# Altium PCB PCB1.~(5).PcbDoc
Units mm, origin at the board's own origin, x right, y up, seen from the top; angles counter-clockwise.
Board outline 152.4 x 101.6 mm, 2 copper layers (Top Layer, Bottom Layer); 19 components, 17 nets, 64 pads, 0 vias.
Unrouted connection lines stored in the file: 41.
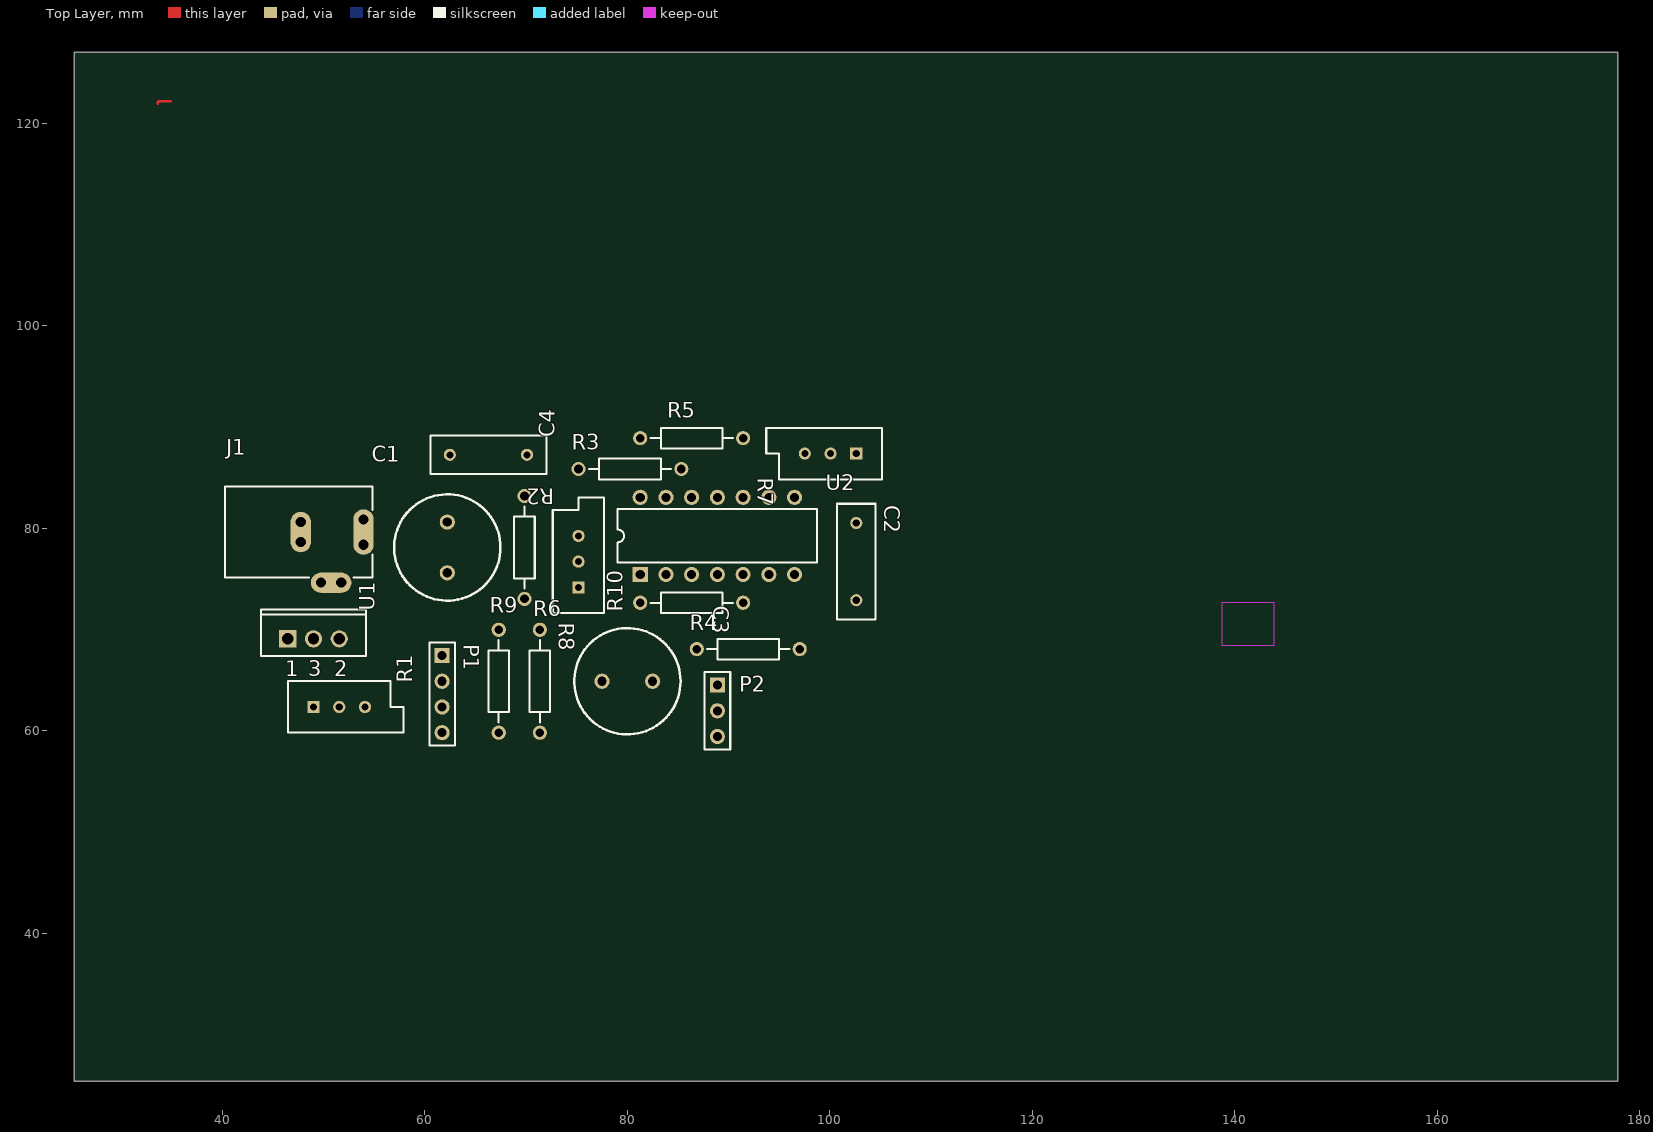
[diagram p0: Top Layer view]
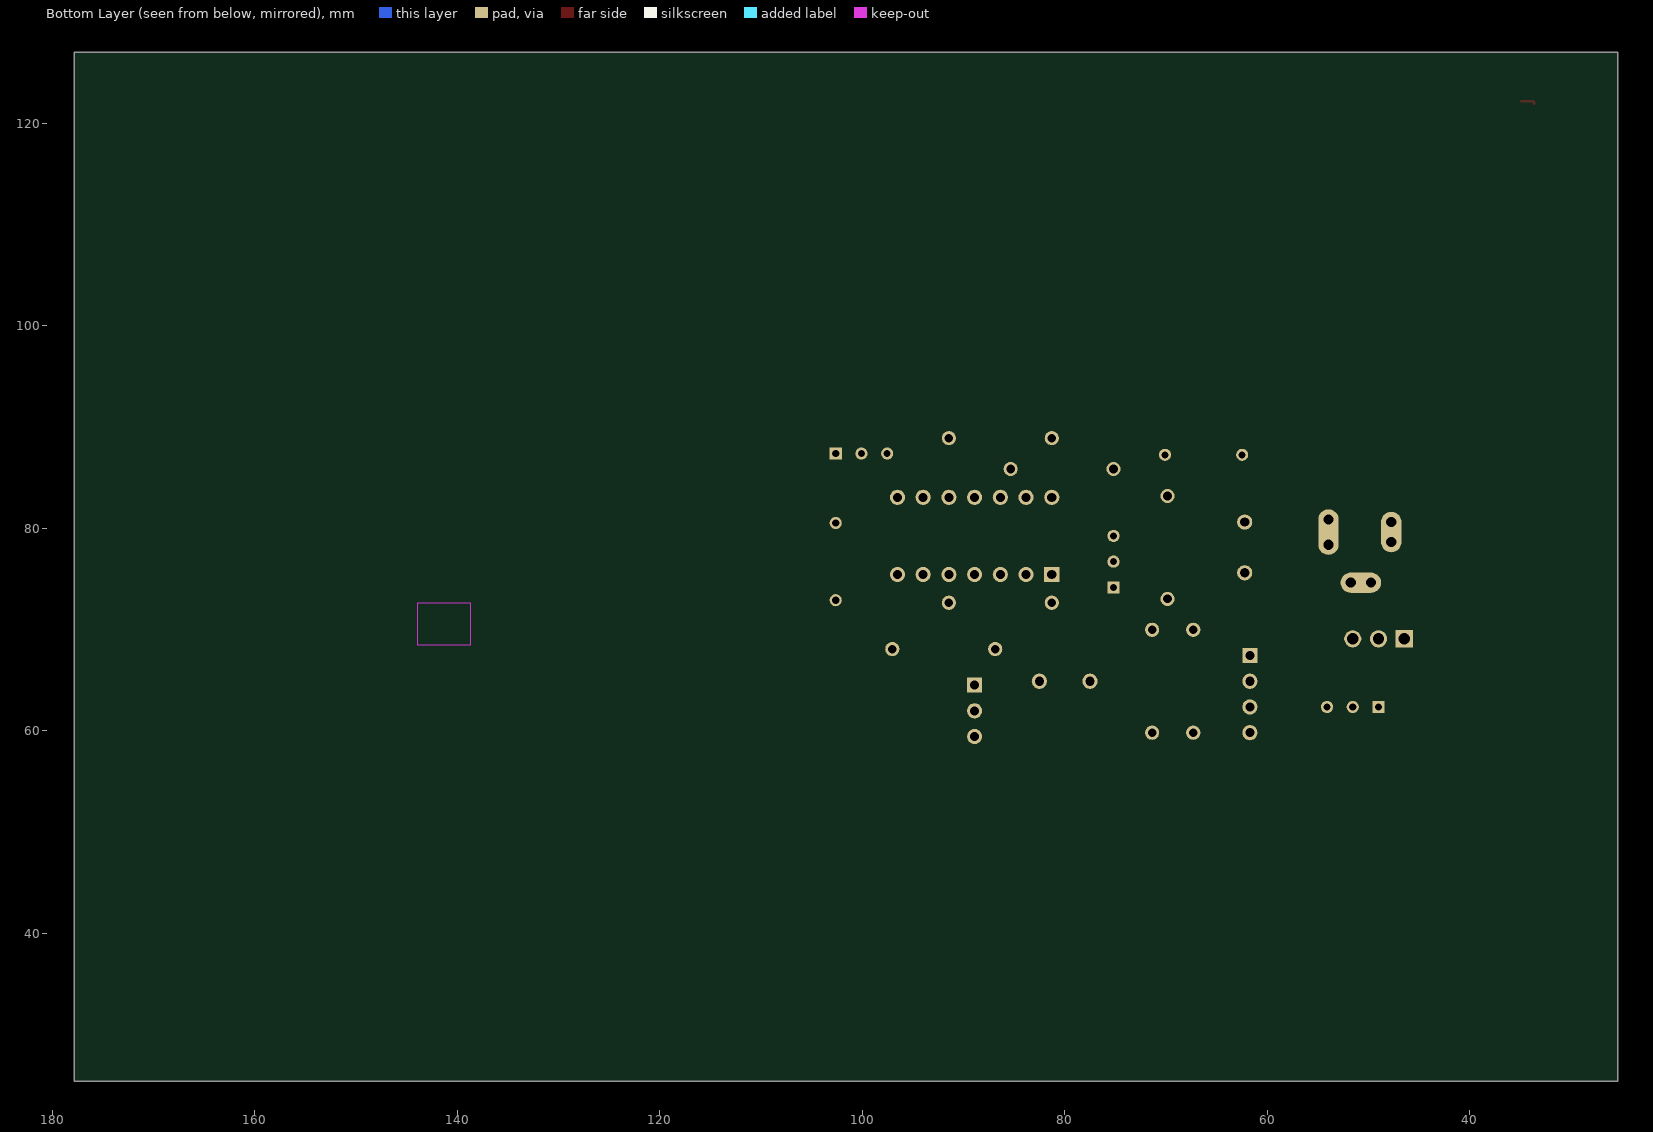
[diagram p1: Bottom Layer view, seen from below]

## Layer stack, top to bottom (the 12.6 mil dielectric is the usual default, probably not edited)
Top Layer: signal copper 0.0356
Dielectric: dielectric 0.32, FR-4, Dk 4.8
Bottom Layer: signal copper 0.0356

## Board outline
25.4,25.4 177.8,25.4 177.8,127 25.4,127

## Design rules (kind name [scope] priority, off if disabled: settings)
Clearance [All] p1: gap=0.254
ComponentClearance [All] p1: gap=0.254 collisioncheckmode=3 verticalgap=0.254
PolygonConnect [All] p1: connectstyle=Relief reliefconductorwidth=0.254 reliefentries=4 polygonreliefangle="90 Angle"
RoomDefinition Sheet1 [InComponentClass('Sheet1')] p1: confinementstyle=ConfineIn formatcopy=TRUE lockcomponents=FALSE outline 26.543,37.846 141.224,37.846 141.224,95.504 26.543,95.504
RoutingTopology [All] p1: topology=Daisy_Balanced
RoutingVias [All] p1: holewidth=0.711 width=2 viastyle="Through Hole" minholewidth=0.711 minwidth=1.27 maxholewidth=0.711 maxwidth=2.27
SolderMaskExpansion [All] p1: expansion=0.102
TestPointUsage [All] p1: valid=0 allowmultiple=FALSE
Testpoint [All] p1: side=15 testpointundercomponent=TRUE minsize=1.016 maxsize=2.54 preferedsize=1.524 minholesize=0 maxholesize=1.016 preferedholesize=0.813 testpointgrid=0.025 style=1023 order=0123456789
Width [All] p1: maxlimit=1254 minlimit=0.254 preferedwidth=0.254 toplayer_maxwidth=1.254 toplayer_prefwidth=0.754 bottomlayer_prefwidth=0.754 minimp=50.000000 maximp=50.000000 favimp=50.000000
17 further rules are at their usual default settings.

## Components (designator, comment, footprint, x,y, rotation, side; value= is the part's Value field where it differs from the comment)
C1 "Cap Pol1" RB5-10.5 62.23,78.105 r270 top
C2 "Cap" RAD-0.3 102.616,76.708 r90 top
C3 "Cap Pol1" RB5-10.5 80.01,64.897 r180 top
C4 "Cap" RAD-0.3 66.294,87.249 r0 top
J1 "PWR2.5" KLD-0202 40.259,79.629 r0 top
P1 "Header 4" HDR1X4 61.722,67.437 r270 top
P2 "Header 3" HDR1X3 88.9,64.516 r270 top
R1 "RPot" VR5 51.562,62.357 r0 top
R2 "RPot" VR5 75.184,76.708 r90 top
R3 "Res2" AXIAL-0.4 80.264,85.852 r180 top
R4 "Res2" AXIAL-0.4 91.948,68.072 r0 top
R5 "Res2" AXIAL-0.4 86.36,88.9 r180 top
R6 "Res2" AXIAL-0.4 69.85,78.105 r270 top
R7 "RPot" VR5 100.076,87.376 r180 top
R8 "Res2" AXIAL-0.4 71.374,64.897 r270 top
R9 "Res2" AXIAL-0.4 67.31,64.897 r90 top
R10 "Res2" AXIAL-0.4 86.36,72.644 r180 top
U1 "L7812ABV" TO220ABN 49.022,69.088 r0 top
U2 "LM324AN" N14A 88.9,79.248 r0 top

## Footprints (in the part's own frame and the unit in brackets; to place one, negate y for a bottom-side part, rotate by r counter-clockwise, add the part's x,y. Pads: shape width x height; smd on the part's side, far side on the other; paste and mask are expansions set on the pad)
AXIAL-0.4 [mm] "Resistor; 2 Leads"
  round 1.4 hole 0.85: 1(-5.08,0) 2(5.08,0)
  silkscreen extent -4.06,-1.02 4.06,1.02
HDR1X3 [mm] "Connector; Header; 3 Position"
  rect 1.5x1.5 hole 0.9: 1(0,0)
  round 1.5 hole 0.9: 2(2.54,0) 3(5.08,0)
  silkscreen extent -1.27,-1.27 6.35,1.27
HDR1X4 [mm] "Connector; Header; 4 Position"
  rect 1.5x1.5 hole 0.9: 1(0,0)
  round 1.5 hole 0.9: 2(2.54,0) 3(5.08,0) 4(7.62,0)
  silkscreen extent -1.27,-1.27 8.89,1.27
KLD-0202 [mm] "DC Power Jack, 2.5mm, KLD Series, PCB Mount"
  oval 2x4.5 all layers, no hole: 1(13.7,0)
  round 1.5 hole 1: 1A(13.7,-1.25) 1B(13.7,1.25) 2A(7.5,-1) 2B(7.5,1) 3A(9.5,-5) 3B(11.5,-5)
  oval 2x4 all layers, no hole: 2(7.5,0)
  oval 4x2 all layers, no hole: 3(10.5,-5)
  silkscreen extent 0,-4.5 14.6,4.5
N14A [mm] "DIP; 14 Leads; Row Spacing 7.62 mm; Pitch 2.54 mm"
  rect 1.5x1.5 hole 0.9: 1(-7.62,-3.81)
  round 1.5 hole 0.9: 2(-5.08,-3.81) 3(-2.54,-3.81) 4(0,-3.81) 5(2.54,-3.81) 6(5.08,-3.81) 7(7.62,-3.81) 8(7.62,3.81) 9(5.08,3.81) 10(2.54,3.81) 11(0,3.81) 12(-2.54,3.81) 13(-5.08,3.81) 14(-7.62,3.81)
  silkscreen extent -9.85,-2.65 9.85,2.65
RAD-0.3 [mm] "Capacitor; 2 Leads"
  round 1.2 hole 0.7: 1(-3.81,0) 2(3.81,0)
  silkscreen extent -5.71,-1.91 5.71,1.91
RB5-10.5 [mm] "Motor, General Kind; 2 Leads"
  round 1.5 hole 0.9: 1(-2.5,0) 2(2.5,0)
  silkscreen extent -5.25,-5.25 5.25,5.25
TO220ABN [mm] "TO, Thru-Hole, Vertical, Heatsink Mounted; 3 In-Line Leads; Pitch 2.54 mm; Pin sequence 1, 3, 2"
  rect 1.7x1.7 hole 1.1: 1(-2.54,0)
  round 1.7 hole 1.1: 2(2.54,0) 3(0,0)
  silkscreen extent -5.2,-1.7 5.2,2.9
VR5 [mm] "Potentiometer; 3 Leads"
  rect 1.2x1.2 hole 0.7: 1(-2.54,0)
  round 1.2 hole 0.7: 2(0,0) 3(2.54,0)
  silkscreen extent -5.08,-2.54 6.35,2.54

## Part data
C1 C3: "Polarized Capacitor (Radial)"
C2 C4: "Capacitor"
J1: "Low Voltage Power Supply Connector"
P1: "Header, 4-Pin"
P2: library part "Header 2", "Header, 2-Pin"
R1 R2 R7: "Potentiometer"
R3 R4 R5 R6 R8 R9 R10: "Resistor"
U1: "Precision 1A Regulator"
U2: "Low-Power Quad Operational Amplifier"

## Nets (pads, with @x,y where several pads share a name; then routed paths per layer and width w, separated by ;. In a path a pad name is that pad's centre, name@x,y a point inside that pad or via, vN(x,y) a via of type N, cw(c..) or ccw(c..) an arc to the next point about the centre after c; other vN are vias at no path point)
+5: C1.2 P1.1 P2.1 R1.2 U1.2 U2.4
GND: C1.1 C3.2 C4.1 J1.1 J1.1A J1.1B P1.4 P2.3 R1.1 R7.2 R8.2 R9.1 R10.2 U1.3 U2.11
NetC2_1: C2.1 R10.1 U2.5
NetC2_2: C2.2 R5.1
NetC3_1: C3.1 R4.1 U2.3
NetC4_2: C4.2 R6.1 U2.12
NetJ1_3: J1.3 J1.3A J1.3B
NetP1_2: P1.2 R6.2 R9.2
NetP1_3: P1.3 R1.3
NetP2_2: P2.2 R7.1 U2.8
NetR2_1: R2.1 R8.1 U2.2
NetR2_2: R2.2 R2.3 R3.2 U2.1
NetR3_1: R3.1 U2.9
NetR4_2: R4.2 U2.6 U2.7
NetR5_2: R5.2 U2.13 U2.14
NetR7_3: R7.3 U2.10
VCC: J1.2 J1.2A J1.2B U1.1
copper on no net: | length 1.4
  Top Layer w0.254: 33.655,121.92 33.655,122.047 33.782,122.174 34.925,122.174

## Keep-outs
Keep-Out Layer:
  rectangle: 138.684,68.453 143.891,72.644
